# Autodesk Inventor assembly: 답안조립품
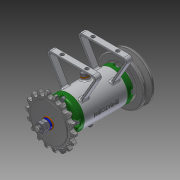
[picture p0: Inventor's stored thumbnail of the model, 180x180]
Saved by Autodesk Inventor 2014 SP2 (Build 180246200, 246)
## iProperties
Created: 2016-03
Part Number: 답안조립품
Document SubType Name: Assembly
Designer: 703
Author: 703
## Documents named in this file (15)
- C:\Users\703\Desktop\460307V1020\답안조립품.iam
- C:\Users\703\Desktop\460307V1020\본체.ipt
- C:\Users\703\Desktop\460307V1020\커버.ipt
- C:\Users\703\Desktop\460307V1020\베어링 15 x 32 x 9.ipt
- C:\Users\703\Desktop\460307V1020\축.ipt
- C:\Users\703\Desktop\460307V1020\볼트 M4 x 12.ipt
- C:\Users\703\Desktop\460307V1020\키 3 x 3 x 12.ipt
- C:\Users\703\Desktop\460307V1020\스프로킷.ipt
- C:\Users\703\Desktop\460307V1020\V벨트풀리.ipt
- C:\Users\703\Desktop\460307V1020\와셔 8x17.ipt
- C:\Users\703\Desktop\460307V1020\스프링와셔 8.ipt
- C:\Users\703\Desktop\460307V1020\너트 M 8.ipt
- C:\Users\703\Desktop\460307V1020\와셔 6x11.5.ipt
- C:\Users\703\Desktop\460307V1020\볼트 M 6 x 8.ipt
- C:\Users\703\Desktop\460307V1020\니플 M 6 x 0.75.ipt
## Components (11 placed, 3 different names)
1. KS B 2023 6002 - 15 x 32 x 9:1
2. KS B 2023 6002 - 15 x 32 x 9:2
3. V벨트풀리:1
4. ISO 4762 M4 x 12:1
5. ISO 4762 M4 x 12:2
6. ISO 4762 M4 x 12:3
7. ISO 4762 M4 x 12:4
8. ISO 4762 M4 x 12:5
9. ISO 4762 M4 x 12:6
10. ISO 4762 M4 x 12:7
11. ISO 4762 M4 x 12:8
